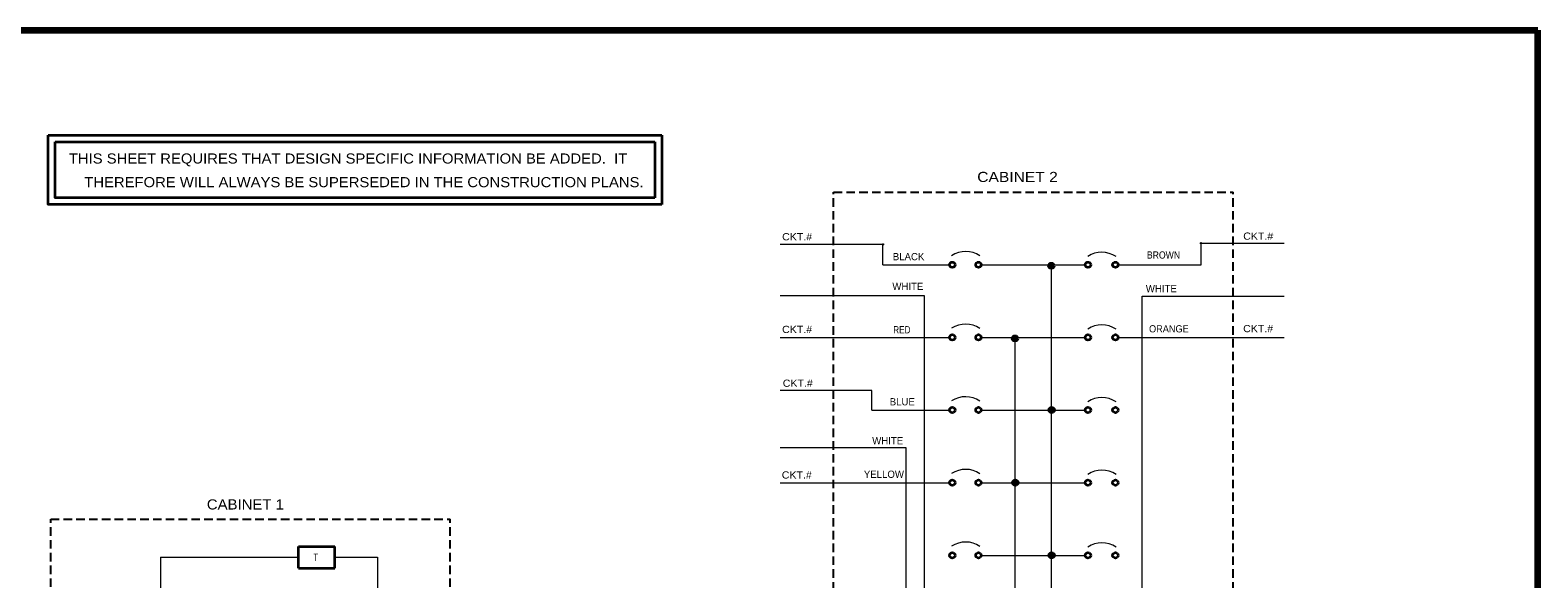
# Model space of a CAD drawing. Extents: x 312583 to 312853, y 144420 to 144585.
# Drawn here: x 312689.8 to 312849, y 144527.2 to 144585.1 of the extents above; entities that cross this region are included whole.
import ezdxf
from ezdxf.enums import TextEntityAlignment as Align

# ---------------------------------------------------------------- set-up
doc = ezdxf.new("R2010")
doc.units = 0
doc.header["$LTSCALE"] = 0.3
doc.header["$PDMODE"] = 32
doc.header["$PDSIZE"] = 0.15
doc.linetypes.add('MEDIUM_DASHED', pattern=[4.5, 3, -1.5])
doc.layers.add('1', color=7, linetype='Continuous', lineweight=13)

msp = doc.modelspace()

# ---------------------------------------------------------------- linework, layer by layer
at = {"layer": '1', "lineweight": 158}
msp.add_line((312849, 144423.1446), (312849, 144585.0846), dxfattribs=at)
at = {"layer": '1', "lineweight": 35}
for p, q in [((312691.7432, 144574.0079), (312756.5112, 144574.0079)), ((312692.4632, 144573.2879), (312755.7912, 144573.2879)), ((312755.7912, 144573.2879), (312755.7912, 144567.3999)), ((312756.5112, 144574.0079), (312756.5112, 144566.6799)), ((312718.162, 144530.6006), (312721.9954, 144530.6006)), ((312718.162, 144528.3006), (312718.162, 144530.6006)), ((312721.9954, 144528.3006), (312721.9954, 144530.6006)), ((312718.162, 144528.3006), (312721.9954, 144528.3006))]:
    msp.add_line(p, q, dxfattribs=at)
at = {"layer": '1', "linetype": 'MEDIUM_DASHED', "lineweight": 25}
for p, q in [((312774.654, 144567.991), (312816.8206, 144567.991)), ((312774.654, 144475.991), (312774.654, 144567.991)), ((312816.8206, 144475.991), (312816.8206, 144567.991)), ((312691.9957, 144533.491), (312734.1624, 144533.491)), ((312691.9957, 144445.3243), (312691.9957, 144533.491)), ((312734.1624, 144445.3243), (312734.1624, 144533.491))]:
    msp.add_line(p, q, dxfattribs=at)
at = {"layer": '1'}
for p, q in [((312779.852, 144562.471), (312769.0036, 144562.471)), ((312779.852, 144560.3243), (312779.852, 144562.471)), ((312813.4473, 144560.3243), (312813.4473, 144562.5936)), ((312813.4473, 144562.5936), (312822.218, 144562.5936)), ((312779.852, 144560.3243), (312786.89, 144560.3243)), ((312790.2403, 144560.3243), (312801.2266, 144560.3243)), ((312797.654, 144487.7823), (312797.654, 144560.3243)), ((312804.692, 144560.3243), (312813.4473, 144560.3243)), ((312784.2373, 144557.0353), (312769.0036, 144557.0353)), ((312784.2373, 144484.6466), (312784.2373, 144557.0353)), ((312807.2373, 144484.5393), (312807.2373, 144556.997)), ((312807.2373, 144556.997), (312822.218, 144556.997)), ((312769.0036, 144552.6576), (312786.8593, 144552.6576)), ((312790.2633, 144552.6576), (312801.2036, 144552.6576)), ((312793.8206, 144487.7746), (312793.8206, 144552.6576)), ((312804.6613, 144552.6346), (312822.218, 144552.6346)), ((312778.702, 144544.991), (312786.8593, 144544.991)), ((312790.2633, 144544.991), (312801.2266, 144544.991)), ((312782.3206, 144540.989), (312769.0036, 144540.989)), ((312782.3206, 144483.9643), (312782.3206, 144540.989)), ((312769.0036, 144537.3243), (312786.8976, 144537.3243)), ((312790.248, 144537.3243), (312801.265, 144537.3243)), ((312703.5954, 144529.466), (312718.162, 144529.466)), ((312703.5954, 144529.466), (312703.5954, 144521.4006)), ((312721.9954, 144529.466), (312726.511, 144529.466)), ((312726.511, 144529.466), (312726.511, 144520.0896)), ((312790.248, 144529.6576), (312801.2343, 144529.6576))]:
    msp.add_line(p, q, dxfattribs=at)
at = {"layer": '1', "lineweight": 158}
msp.add_lwpolyline([(312616.5, 144423.1446), (312616.5, 144585.0846), (312849, 144585.0846)], dxfattribs=at)
at = {"layer": '1', "lineweight": 35}
for points in [[(312756.5112, 144566.6799), (312691.7432, 144566.6799), (312691.7432, 144574.0079)], [(312755.7912, 144567.3999), (312692.4632, 144567.3999), (312692.4632, 144573.2879)]]:
    msp.add_lwpolyline(points, dxfattribs=at)
at = {"layer": '1'}
msp.add_lwpolyline([(312778.702, 144544.991), (312778.702, 144547.0533), (312769.0036, 144547.0533)], dxfattribs=at)
at = {"layer": '1', "lineweight": 35}
for centre, radius in [((312787.1813, 144560.3245), 0.2897), ((312789.9413, 144560.3245), 0.2897), ((312797.6312, 144560.217), 0.2897), ((312797.631, 144560.217), 0.23), ((312797.631, 144560.217), 0.1533), ((312797.631, 144560.217), 0.0767), ((312801.5026, 144560.3245), 0.2897), ((312804.4006, 144560.3245), 0.2897), ((312787.1813, 144552.6579), 0.2897), ((312789.9413, 144552.6579), 0.2897), ((312793.7979, 144552.5503), 0.2897), ((312793.7976, 144552.5503), 0.23), ((312793.7976, 144552.5503), 0.1533), ((312793.7976, 144552.5503), 0.0767), ((312801.5026, 144552.6579), 0.2897), ((312804.4006, 144552.6579), 0.2897), ((312787.1813, 144544.9912), 0.2897), ((312789.9413, 144544.9912), 0.2897), ((312797.6695, 144544.991), 0.2897), ((312797.6693, 144544.991), 0.23), ((312797.6693, 144544.991), 0.1533), ((312797.6693, 144544.991), 0.0767), ((312801.5026, 144544.9912), 0.2897), ((312804.4006, 144544.9912), 0.2897), ((312787.1813, 144537.3245), 0.2897), ((312789.9413, 144537.3245), 0.2897), ((312793.8362, 144537.3243), 0.2897), ((312793.836, 144537.3243), 0.23), ((312793.836, 144537.3243), 0.1533), ((312793.836, 144537.3243), 0.0767), ((312801.5026, 144537.3245), 0.2897), ((312804.4006, 144537.3245), 0.2897), ((312787.1813, 144529.6579), 0.2897), ((312789.9413, 144529.6579), 0.2897), ((312797.6695, 144529.6576), 0.2897), ((312797.6693, 144529.6576), 0.23), ((312797.6693, 144529.6576), 0.1533), ((312797.6693, 144529.6576), 0.0767), ((312801.5026, 144529.6579), 0.2897), ((312804.4006, 144529.6579), 0.2897)]:
    msp.add_circle(centre, radius, dxfattribs=at)
at = {"layer": '1'}
for centre in [(312788.5959, 144559.0518), (312802.9632, 144558.9674), (312788.5959, 144551.3851), (312802.9632, 144551.3008), (312788.5959, 144543.7184), (312802.9632, 144543.6341), (312788.5959, 144536.0518), (312802.9632, 144535.9674), (312788.5959, 144528.3851), (312802.9632, 144528.3008)]:
    msp.add_arc(centre, 2.6791, 55.78717, 123.62519, dxfattribs=at)
for p in [(312779.852, 144562.471), (312813.4473, 144562.5936)]:
    msp.add_point(p, dxfattribs=at)

# ---------------------------------------------------------------- texts
at = {"layer": '1', "width": 1.1}
for s, p in [('THIS SHEET REQUIRES THAT DESIGN SPECIFIC INFORMATION BE ADDED.  IT', (312723.388, 144571.0079)), ('THEREFORE WILL ALWAYS BE SUPERSEDED IN THE CONSTRUCTION PLANS.', (312725.0636, 144568.5119))]:
    msp.add_text(s, height=1.064, dxfattribs=at).set_placement(p, align=Align.CENTER)
at = {"layer": '1'}
for s, height, width, p in [('CABINET 2', 1.07, 1.15, (312789.8138, 144569.0602)), ('CKT.#', 0.76, 1.1, (312769.213, 144562.9031)), ('CKT.#', 0.76, 1.1, (312817.8952, 144562.9683)), ('BROWN', 0.76, 0.9, (312807.724, 144560.975)), ('ORANGE', 0.76, 0.95, (312807.9549, 144553.1857)), ('CKT.#', 0.76, 1.1, (312817.8875, 144553.2086)), ('CKT.#', 0.76, 1.1, (312769.2129, 144553.1243)), ('RED', 0.76, 0.85, (312780.9442, 144553.0879)), ('CKT.#', 0.76, 1.1, (312769.2839, 144547.4471)), ('CKT.#', 0.76, 1.1, (312769.1785, 144537.7585)), ('CABINET 1', 1.07, 1.1, (312708.4792, 144534.495)), ('T', 0.76, 0.8, (312719.7288, 144529.0701))]:
    msp.add_text(s, height=height, dxfattribs=dict(at, width=width)).set_placement(p)
for s, p in [('BLACK', (312780.8965, 144560.8006)), ('WHITE', (312780.8515, 144557.6688)), ('WHITE', (312807.6128, 144557.4254)), ('BLUE', (312780.5734, 144545.4865)), ('WHITE', (312778.7223, 144541.3751)), ('YELLOW', (312777.8433, 144537.8369))]:
    msp.add_text(s, height=0.76, dxfattribs=at).set_placement(p)

doc.saveas('drawing.dxf')
